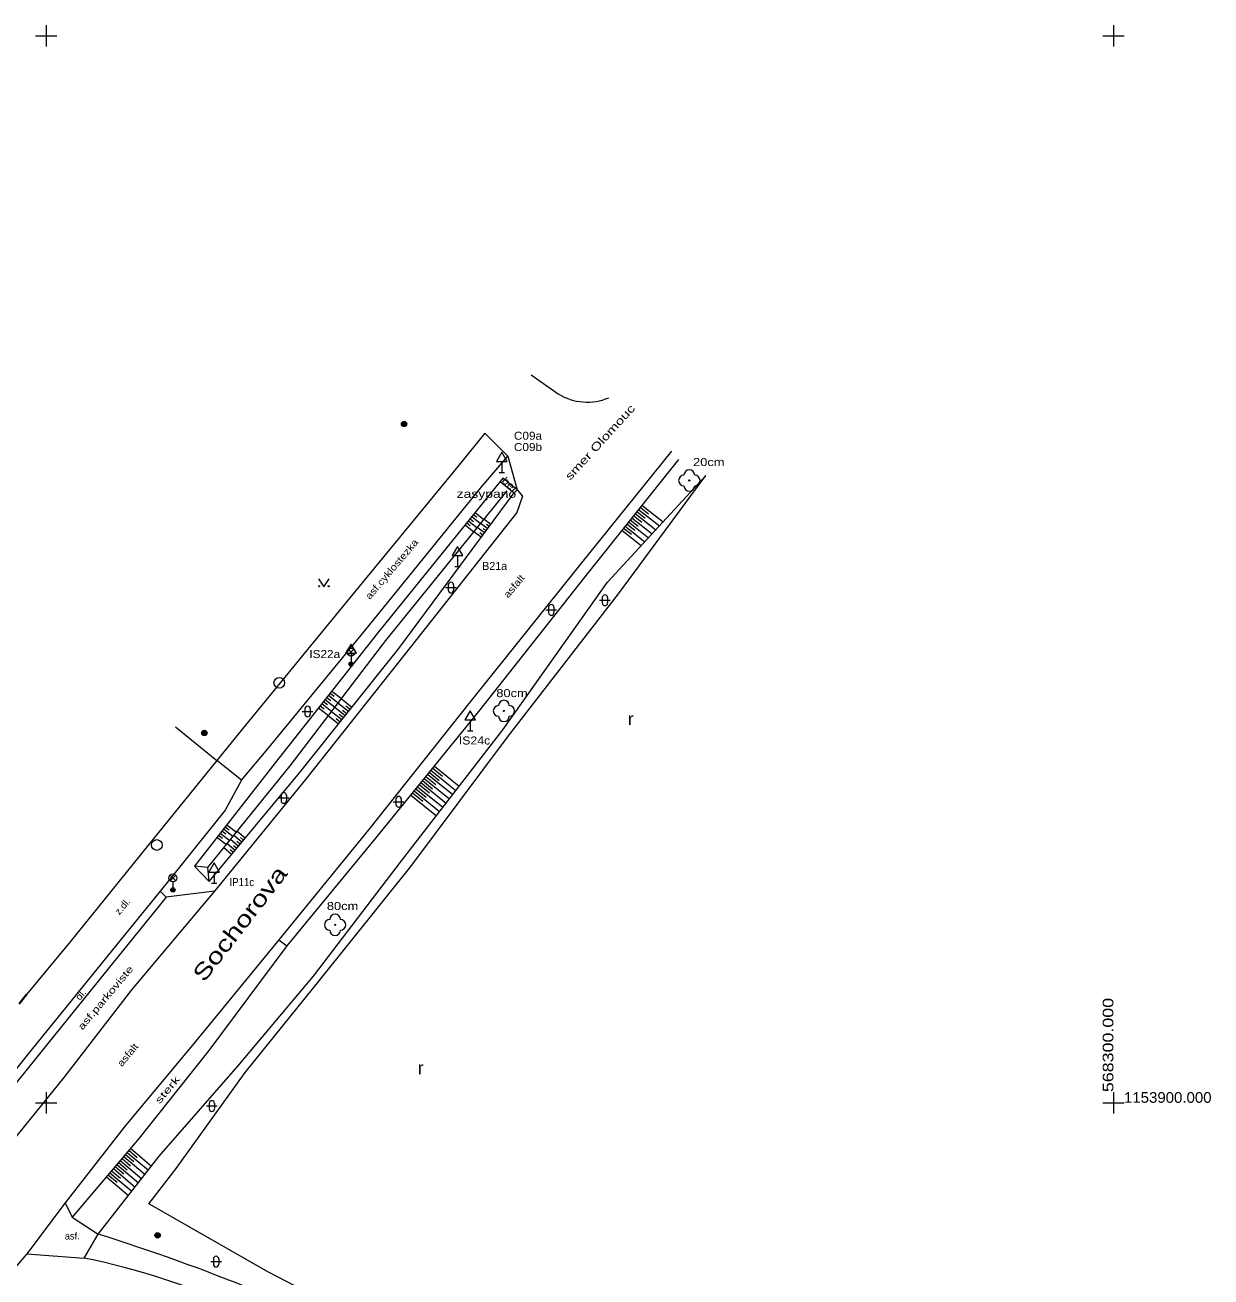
# Model space of a CAD drawing. Extents: x -568501 to -568291, y -1154101 to -1153799.
# Drawn here: x -568402 to -568290.9, y -1153916.3 to -1153799 of the extents above; entities that cross this region are included whole.
import ezdxf
from ezdxf.enums import TextEntityAlignment as Align

# ---------------------------------------------------------------- set-up
doc = ezdxf.new("R2010")
doc.units = 0
doc.header["$LTSCALE"] = 0.3
for name, color, linetype, lineweight in [('10', 7, 'Continuous', 13), ('11', 7, 'Continuous', 13), ('14', 7, 'Continuous', 13), ('15', 7, 'Continuous', 13), ('22', 7, 'Continuous', 13), ('23', 7, 'Continuous', 13), ('25', 7, 'Continuous', 13), ('27', 7, 'Continuous', 13), ('33', 7, 'Continuous', 13), ('34', 7, 'Continuous', 13), ('36', 7, 'Continuous', 13), ('42', 7, 'Continuous', 13), ('61', 7, 'Continuous', 13), ('7', 7, 'Continuous', 13), ('8', 7, 'Continuous', 35)]:
    doc.layers.add(name, color=color, linetype=linetype, lineweight=lineweight)
doc.layers.add('40', color=7, linetype='Continuous')
doc.layers.add('49', color=7, linetype='Continuous')

msp = doc.modelspace()

# ---------------------------------------------------------------- linework, layer by layer
at = {"layer": '10'}
msp.add_line((-568354.56, -1153831.77), (-568352.01, -1153833.56), dxfattribs=at)
for points in [[(-568358.89, -1153837.25), (-568356.74, -1153839.4), (-568355.85, -1153842.56), (-568355.35, -1153843.15), (-568355.9, -1153844.67)], [(-568341.41, -1153838.94), (-568349.83, -1153849.41), (-568360.25, -1153862.43), (-568369.78, -1153874.42), (-568378.19, -1153884.73), (-568386.01, -1153894.27), (-568392.67, -1153902.27), (-568398.22, -1153909.37), (-568401.79, -1153914.15), (-568403.6, -1153916.28)], [(-568355.9, -1153844.67), (-568366.36, -1153857.91), (-568375.7, -1153869.7), (-568384.23, -1153880.16)], [(-568384.23, -1153880.16), (-568392.01, -1153889.4), (-568398.35, -1153897.64), (-568404.75, -1153905.51), (-568410.43, -1153912.49)]]:
    msp.add_lwpolyline(points, dxfattribs=at)
msp.add_arc((-568349.2898, -1153829.2037), 5.1358, 238.01773, 293.03667, dxfattribs=at)
at = {"layer": '11'}
for p, q in [((-568381.7, -1153869.78), (-568384, -1153867.91)), ((-568388.74, -1153880.73), (-568389.32, -1153880.18)), ((-568378.19, -1153884.73), (-568377.44, -1153885.3))]:
    msp.add_line(p, q, dxfattribs=at)
for points in [[(-568358.89, -1153837.25), (-568361.41, -1153840.38), (-568372.26, -1153853.55), (-568381.59, -1153864.95), (-568384, -1153867.91)], [(-568381.7, -1153869.78), (-568379.23, -1153866.82), (-568369.76, -1153855.31), (-568359.16, -1153842.23), (-568356.74, -1153839.4)], [(-568381.7, -1153869.78), (-568383.21, -1153872.58), (-568387.5, -1153877.91), (-568389.32, -1153880.18), (-568394.71, -1153886.81), (-568401.41, -1153895.07), (-568405.07, -1153899.62), (-568408.29, -1153903.1), (-568410.38, -1153905.27)], [(-568384.23, -1153880.16), (-568388.74, -1153880.73), (-568394.35, -1153887.63), (-568400.75, -1153895.57), (-568404.48, -1153900.2), (-568404.75, -1153905.51)], [(-568377.44, -1153885.3), (-568384.74, -1153895.11), (-568391.27, -1153903.31), (-568397.56, -1153910.73)], [(-568398.22, -1153909.37), (-568397.56, -1153910.73), (-568395.11, -1153912.31)], [(-568401.79, -1153914.15), (-568396.43, -1153914.55), (-568395.11, -1153912.31)]]:
    msp.add_lwpolyline(points, dxfattribs=at)
msp.add_lwpolyline([(-568356.13, -1153842.84), (-568355.85, -1153842.56), (-568357.21, -1153841.45), (-568357.45, -1153841.79)], close=True, dxfattribs=at)
for centre, radius, start, end in [((-568450.7473, -1154089.926), 186.1261, 67.78962, 72.60711), ((-568410.9033, -1153984.3733), 71.3076, 65.55079, 78.28935)]:
    msp.add_arc(centre, radius, start, end, dxfattribs=at)
at = {"layer": '14'}
for points in [[(-568340.75, -1153839.71), (-568349.18, -1153850.27), (-568359.47, -1153863.33), (-568369.12, -1153875.21), (-568377.44, -1153885.3)], [(-568395.11, -1153912.31), (-568389.39, -1153905.01), (-568382.04, -1153896.57), (-568374.93, -1153888.14), (-568366.7, -1153877.32), (-568357.21, -1153865.06), (-568347.39, -1153851.22), (-568338.19, -1153841.21)], [(-568357.45, -1153841.79), (-568368.95, -1153855.98), (-568378.18, -1153867.7), (-568386.1, -1153877.81), (-568384.71, -1153879.25), (-568384.84, -1153877.95), (-568386.1, -1153877.81)], [(-568384.84, -1153877.95), (-568377.13, -1153868.43), (-568368.18, -1153856.68), (-568356.81, -1153842.64)], [(-568384.71, -1153879.25), (-568376.25, -1153869.09), (-568366.96, -1153857.43), (-568356.13, -1153842.84)]]:
    msp.add_lwpolyline(points, dxfattribs=at)
at = {"layer": '15'}
for p, q in [((-568344.482, -1153844.385), (-568342.536, -1153845.939)), ((-568344.326, -1153844.19), (-568343.542, -1153844.815)), ((-568344.17, -1153843.994), (-568342.197, -1153845.57)), ((-568360.578, -1153845.65), (-568360.257, -1153845.91)), ((-568360.421, -1153845.455), (-568359.617, -1153846.106)), ((-568360.263, -1153845.261), (-568359.942, -1153845.522)), ((-568360.106, -1153845.067), (-568359.303, -1153845.718)), ((-568359.948, -1153844.873), (-568359.627, -1153845.133)), ((-568359.791, -1153844.679), (-568358.988, -1153845.329)), ((-568358.623, -1153846.198), (-568359.29, -1153845.703)), ((-568358.325, -1153845.797), (-568358.975, -1153845.314)), ((-568345.418, -1153845.557), (-568343.553, -1153847.046)), ((-568345.262, -1153845.362), (-568344.511, -1153845.962)), ((-568345.106, -1153845.167), (-568343.214, -1153846.677)), ((-568344.95, -1153844.971), (-568344.188, -1153845.58)), ((-568344.794, -1153844.776), (-568342.875, -1153846.308)), ((-568344.638, -1153844.58), (-568343.865, -1153845.197)), ((-568360.735, -1153845.844), (-568359.932, -1153846.495)), ((-568359.219, -1153847.001), (-568359.92, -1153846.48)), ((-568358.921, -1153846.6), (-568359.605, -1153846.092)), ((-568359.07, -1153846.8), (-568359.347, -1153846.595)), ((-568358.772, -1153846.399), (-568359.042, -1153846.198)), ((-568358.474, -1153845.997), (-568358.737, -1153845.802)), ((-568346.042, -1153846.339), (-568344.232, -1153847.784)), ((-568345.886, -1153846.143), (-568345.156, -1153846.726)), ((-568345.73, -1153845.948), (-568343.893, -1153847.415)), ((-568345.574, -1153845.753), (-568344.834, -1153846.344)), ((-568373.693, -1153862.003), (-568373.328, -1153862.29)), ((-568373.538, -1153861.806), (-568372.63, -1153862.522)), ((-568373.384, -1153861.61), (-568373.021, -1153861.895)), ((-568373.229, -1153861.413), (-568372.327, -1153862.124)), ((-568374.466, -1153862.985), (-568373.539, -1153863.715)), ((-568374.312, -1153862.788), (-568373.942, -1153863.079)), ((-568374.157, -1153862.592), (-568373.236, -1153863.317)), ((-568374.002, -1153862.395), (-568373.635, -1153862.685)), ((-568373.848, -1153862.199), (-568372.933, -1153862.92)), ((-568371.979, -1153863.729), (-568372.956, -1153862.951)), ((-568371.667, -1153863.338), (-568372.653, -1153862.553)), ((-568371.356, -1153862.947), (-568372.35, -1153862.155)), ((-568371.823, -1153863.534), (-568372.216, -1153863.221)), ((-568371.512, -1153863.143), (-568371.908, -1153862.827)), ((-568372.602, -1153864.512), (-568373.562, -1153863.746)), ((-568372.291, -1153864.12), (-568373.259, -1153863.349)), ((-568372.446, -1153864.316), (-568372.832, -1153864.009)), ((-568372.135, -1153863.925), (-568372.524, -1153863.615)), ((-568364.093, -1153869.021), (-568363.155, -1153869.782)), ((-568363.935, -1153868.827), (-568361.596, -1153870.727)), ((-568363.778, -1153868.633), (-568362.844, -1153869.391)), ((-568363.62, -1153868.439), (-568361.29, -1153870.331)), ((-568365.039, -1153870.185), (-568364.09, -1153870.956)), ((-568364.881, -1153869.991), (-568362.515, -1153871.913)), ((-568364.723, -1153869.797), (-568363.779, -1153870.565)), ((-568364.566, -1153869.603), (-568362.209, -1153871.518)), ((-568364.408, -1153869.409), (-568363.467, -1153870.173)), ((-568364.25, -1153869.215), (-568361.903, -1153871.122)), ((-568365.827, -1153871.156), (-568363.433, -1153873.1)), ((-568365.669, -1153870.962), (-568364.713, -1153871.738)), ((-568365.511, -1153870.767), (-568363.127, -1153872.704)), ((-568365.354, -1153870.573), (-568364.402, -1153871.347)), ((-568365.196, -1153870.379), (-568362.821, -1153872.309)), ((-568383.835, -1153874.919), (-568383.48, -1153875.197)), ((-568383.681, -1153874.722), (-568382.791, -1153875.419)), ((-568383.527, -1153874.525), (-568383.169, -1153874.805)), ((-568383.372, -1153874.328), (-568382.476, -1153875.031)), ((-568383.218, -1153874.131), (-568382.858, -1153874.413)), ((-568383.064, -1153873.935), (-568382.161, -1153874.642)), ((-568381.655, -1153875.581), (-568382.412, -1153874.951)), ((-568381.335, -1153875.197), (-568382.097, -1153874.563)), ((-568383.989, -1153875.116), (-568383.105, -1153875.808)), ((-568382.615, -1153876.734), (-568383.356, -1153876.117)), ((-568382.295, -1153876.35), (-568383.041, -1153875.729)), ((-568381.975, -1153875.966), (-568382.726, -1153875.34)), ((-568382.135, -1153876.158), (-568382.435, -1153875.908)), ((-568381.815, -1153875.773), (-568382.117, -1153875.522)), ((-568381.495, -1153875.389), (-568381.799, -1153875.136)), ((-568382.455, -1153876.542), (-568382.752, -1153876.294)), ((-568392.078, -1153904.263), (-568390.111, -1153905.93)), ((-568393.048, -1153905.407), (-568391.037, -1153907.112)), ((-568392.886, -1153905.216), (-568392.085, -1153905.896)), ((-568392.724, -1153905.026), (-568390.728, -1153906.718)), ((-568392.563, -1153904.835), (-568391.767, -1153905.509)), ((-568392.401, -1153904.644), (-568390.419, -1153906.324)), ((-568392.239, -1153904.453), (-568391.45, -1153905.123)), ((-568394.018, -1153906.551), (-568391.963, -1153908.293)), ((-568393.856, -1153906.36), (-568393.037, -1153907.055)), ((-568393.694, -1153906.17), (-568391.654, -1153907.899)), ((-568393.533, -1153905.979), (-568392.719, -1153906.668)), ((-568393.371, -1153905.788), (-568391.345, -1153907.505)), ((-568393.209, -1153905.598), (-568392.402, -1153906.282)), ((-568394.341, -1153906.933), (-568392.271, -1153908.687)), ((-568394.179, -1153906.742), (-568393.354, -1153907.441))]:
    msp.add_line(p, q, dxfattribs=at)
at = {"layer": '22'}
for centre in [(-568339.73, -1153841.68), (-568357.1, -1153863.28), (-568372.92, -1153883.32)]:
    msp.add_circle(centre, 0.05, dxfattribs=at)
for centre, start, end in [((-568339.73, -1153841.18), 0, 180), ((-568340.23, -1153841.68), 90, 270), ((-568339.73, -1153842.18), 180, 0), ((-568339.23, -1153841.68), 270, 90), ((-568357.6, -1153863.28), 90, 270), ((-568357.1, -1153862.78), 0, 180), ((-568356.6, -1153863.28), 270, 90), ((-568357.1, -1153863.78), 180, 0), ((-568373.42, -1153883.32), 90, 270), ((-568372.92, -1153882.82), 0, 180), ((-568372.42, -1153883.32), 270, 90), ((-568372.92, -1153883.82), 180, 0)]:
    msp.add_arc(centre, 0.5, start, end, dxfattribs=at)
at = {"layer": '23'}
msp.add_lwpolyline([(-568354.04, -1153929.41), (-568364.61, -1153923.44), (-568379.16, -1153915.86), (-568390.37, -1153909.46), (-568387.81, -1153906.15), (-568381.36, -1153897.16), (-568374.28, -1153888.42), (-568365.82, -1153877.84), (-568356.68, -1153865.62), (-568346.38, -1153852.31), (-568338.19, -1153841.21)], dxfattribs=at)
at = {"layer": '25'}
for centre, radius in [((-568366.46, -1153836.38), 0.25), ((-568366.46, -1153836.38), 0.2), ((-568366.46, -1153836.38), 0.15), ((-568366.46, -1153836.38), 0.1), ((-568366.46, -1153836.38), 0.05), ((-568385.17, -1153865.34), 0.25), ((-568385.17, -1153865.34), 0.2), ((-568385.17, -1153865.34), 0.15), ((-568385.17, -1153865.34), 0.1), ((-568385.17, -1153865.34), 0.05), ((-568389.55, -1153912.42), 0.25), ((-568389.55, -1153912.42), 0.2), ((-568389.55, -1153912.42), 0.15), ((-568389.55, -1153912.42), 0.1), ((-568389.55, -1153912.42), 0.05)]:
    msp.add_circle(centre, radius, dxfattribs=at)
at = {"layer": '27'}
for centre in [(-568378.15, -1153860.64), (-568389.62, -1153875.84)]:
    msp.add_circle(centre, 0.5, dxfattribs=at)
at = {"layer": '33'}
for p, q in [((-568371.695, -1153858.03), (-568371.165, -1153857.5)), ((-568371.695, -1153857.5), (-568371.165, -1153858.03)), ((-568371.43, -1153858.14), (-568371.43, -1153858.89)), ((-568388.385, -1153879.19), (-568387.855, -1153878.66)), ((-568388.385, -1153878.66), (-568387.855, -1153879.19)), ((-568388.12, -1153879.3), (-568388.12, -1153880.05))]:
    msp.add_line(p, q, dxfattribs=at)
for centre, radius in [((-568371.43, -1153857.765), 0.375), ((-568371.43, -1153858.89), 0.2), ((-568371.43, -1153858.89), 0.1445), ((-568371.43, -1153858.89), 0.0876), ((-568388.12, -1153878.925), 0.375), ((-568388.12, -1153880.05), 0.2), ((-568388.12, -1153880.05), 0.1445), ((-568388.12, -1153880.05), 0.0876)]:
    msp.add_circle(centre, radius, dxfattribs=at)
at = {"layer": '34'}
for p, q in [((-568357.55, -1153840.92), (-568357.05, -1153840.92)), ((-568357.3, -1153839.902), (-568357.3, -1153840.92)), ((-568361.44, -1153848.722), (-568361.44, -1153849.74)), ((-568361.69, -1153849.74), (-568361.19, -1153849.74)), ((-568371.43, -1153857.872), (-568371.43, -1153858.89)), ((-568360.28, -1153864.122), (-568360.28, -1153865.14)), ((-568360.53, -1153865.14), (-568360.03, -1153865.14)), ((-568384.24, -1153878.392), (-568384.24, -1153879.41)), ((-568384.49, -1153879.41), (-568383.99, -1153879.41))]:
    msp.add_line(p, q, dxfattribs=at)
for points in [[(-568357.8, -1153839.902), (-568356.8, -1153839.902), (-568357.3, -1153839.036)], [(-568361.94, -1153848.722), (-568360.94, -1153848.722), (-568361.44, -1153847.856)], [(-568371.93, -1153857.872), (-568370.93, -1153857.872), (-568371.43, -1153857.006)], [(-568360.78, -1153864.122), (-568359.78, -1153864.122), (-568360.28, -1153863.256)], [(-568384.74, -1153878.392), (-568383.74, -1153878.392), (-568384.24, -1153877.526)]]:
    msp.add_lwpolyline(points, close=True, dxfattribs=at)
at = {"layer": '36'}
for p, q in [((-568362.312, -1153851.467), (-568362.312, -1153851.967)), ((-568361.812, -1153851.467), (-568361.812, -1153851.967)), ((-568362.562, -1153851.717), (-568361.562, -1153851.717)), ((-568347.882, -1153852.657), (-568347.882, -1153853.157)), ((-568347.382, -1153852.657), (-568347.382, -1153853.157)), ((-568353.168, -1153853.815), (-568352.168, -1153853.815)), ((-568352.918, -1153853.565), (-568352.918, -1153854.065)), ((-568352.418, -1153853.565), (-568352.418, -1153854.065)), ((-568348.132, -1153852.907), (-568347.132, -1153852.907)), ((-568375.742, -1153863.075), (-568375.742, -1153863.575)), ((-568375.242, -1153863.075), (-568375.242, -1153863.575)), ((-568375.992, -1153863.325), (-568374.992, -1153863.325)), ((-568378.231, -1153871.431), (-568377.231, -1153871.431)), ((-568377.981, -1153871.181), (-568377.981, -1153871.681)), ((-568377.481, -1153871.181), (-568377.481, -1153871.681)), ((-568367.465, -1153871.782), (-568366.465, -1153871.782)), ((-568367.215, -1153871.532), (-568367.215, -1153872.032)), ((-568366.715, -1153871.532), (-568366.715, -1153872.032)), ((-568384.969, -1153900.298), (-568383.969, -1153900.298)), ((-568384.719, -1153900.048), (-568384.719, -1153900.548)), ((-568384.219, -1153900.048), (-568384.219, -1153900.548)), ((-568384.576, -1153914.88), (-568383.576, -1153914.88)), ((-568384.326, -1153914.63), (-568384.326, -1153915.13)), ((-568383.826, -1153914.63), (-568383.826, -1153915.13))]:
    msp.add_line(p, q, dxfattribs=at)
msp.add_lwpolyline([(-568374.47, -1153850.893), (-568373.97, -1153851.643), (-568373.47, -1153850.893)], dxfattribs=at)
for centre in [(-568374.4206, -1153851.5927), (-568373.5212, -1153851.5927)]:
    msp.add_circle(centre, 0.05, dxfattribs=at)
for centre, start, end in [((-568362.0622, -1153851.4692), 0, 180), ((-568362.0622, -1153851.9692), 180, 0), ((-568347.6321, -1153852.6587), 0, 180), ((-568352.6682, -1153853.5671), 0, 180), ((-568347.6321, -1153853.1587), 180, 0), ((-568352.6682, -1153854.0671), 180, 0), ((-568375.4922, -1153863.0771), 0, 180), ((-568375.4922, -1153863.5771), 180, 0), ((-568377.7315, -1153871.1828), 0, 180), ((-568366.9648, -1153871.534), 0, 180), ((-568377.7315, -1153871.6828), 180, 0), ((-568366.9648, -1153872.034), 180, 0), ((-568384.4694, -1153900.0494), 0, 180), ((-568384.4694, -1153900.5494), 180, 0), ((-568384.0761, -1153914.6315), 0, 180), ((-568384.0761, -1153915.1315), 180, 0)]:
    msp.add_arc(centre, 0.25, start, end, dxfattribs=at)
at = {"layer": '61'}
for p, q in [((-568400, -1153799), (-568400, -1153801)), ((-568300, -1153799), (-568300, -1153801)), ((-568401, -1153800), (-568399, -1153800)), ((-568301, -1153800), (-568299, -1153800)), ((-568400, -1153899), (-568400, -1153901)), ((-568300, -1153899), (-568300, -1153901)), ((-568401, -1153900), (-568399, -1153900)), ((-568301, -1153900), (-568299, -1153900))]:
    msp.add_line(p, q, dxfattribs=at)
at = {"layer": '7'}
msp.add_line((-568387.886, -1153864.764), (-568384, -1153867.91), dxfattribs=at)
msp.add_lwpolyline([(-568384, -1153867.91), (-568390.54, -1153875.99), (-568397.75, -1153884.92), (-568401.83, -1153889.84)], dxfattribs=at)
at = {"layer": '8'}
msp.add_line((-568402.52, -1153890.74), (-568401.83, -1153889.84), dxfattribs=at)

# ---------------------------------------------------------------- texts
at = {"layer": '36'}
for p in [(-568345.2195, -1153864.609), (-568364.9025, -1153897.319)]:
    msp.add_text('r', height=1.2, dxfattribs=at).set_placement(p, align=Align.CENTER)
at = {"layer": '40'}
for s, rotation, width, p in [('bet.', 315.978, 1.3, (-568357.348, -1153841.741)), ('asf.cyklostezka', 49.573, 1.2, (-568369.662, -1153852.89)), ('asfalt', 50.073, 1.2, (-568356.702, -1153852.75)), ('z.dl.', 49.573, 1.05, (-568393.137, -1153882.443)), ('asf.parkoviste', 50.073, 1.4, (-568396.594, -1153893.243)), ('dl.', 49.573, 1.1, (-568396.84, -1153890.453)), ('asfalt', 50.073, 1.2, (-568392.897, -1153896.666)), ('sterk', 50.073, 1.6, (-568389.351, -1153900.143))]:
    msp.add_text(s, height=0.65, rotation=rotation, dxfattribs=dict(at, width=width)).set_placement(p)
msp.add_text('asf.', height=0.65, dxfattribs=at).set_placement((-568398.249, -1153912.808))
at = {"layer": '42', "width": 1.4}
msp.add_text('smer Olomouc', height=0.75, rotation=47.66, dxfattribs=at).set_placement((-568347.8222, -1153838.3476), align=Align.CENTER)
at = {"layer": '42'}
for s, width, p in [('C09a', 1.1, (-568354.8455, -1153837.863)), ('C09b', 1.1, (-568354.8455, -1153838.92)), ('20cm', 1.2, (-568337.9085, -1153840.328)), ('zasypano', 1.3, (-568358.7435, -1153843.307)), ('IS22a', 1.1, (-568373.8895, -1153858.322)), ('80cm', 1.2, (-568356.3445, -1153861.984)), ('IS24c', 1.15, (-568359.858, -1153866.422)), ('IP11c', 0.9, (-568381.6625, -1153879.69)), ('80cm', 1.2, (-568372.2205, -1153881.931))]:
    msp.add_text(s, height=0.75, dxfattribs=dict(at, width=width)).set_placement(p, align=Align.CENTER)
msp.add_text('B21a', height=0.75, dxfattribs=at).set_placement((-568357.97, -1153850.064), align=Align.CENTER)
at = {"layer": '49', "width": 1.35}
msp.add_text('Sochorova', height=1.5, rotation=52.355, dxfattribs=at).set_placement((-568385.198, -1153888.782))
at = {"layer": '61', "width": 1.25}
msp.add_text('568300.000', height=1, rotation=90, dxfattribs=at).set_placement((-568300, -1153899))
at = {"layer": '61', "width": 1.05}
msp.add_text('1153900.000', height=1, dxfattribs=at).set_placement((-568299, -1153900))

doc.saveas('drawing.dxf')
